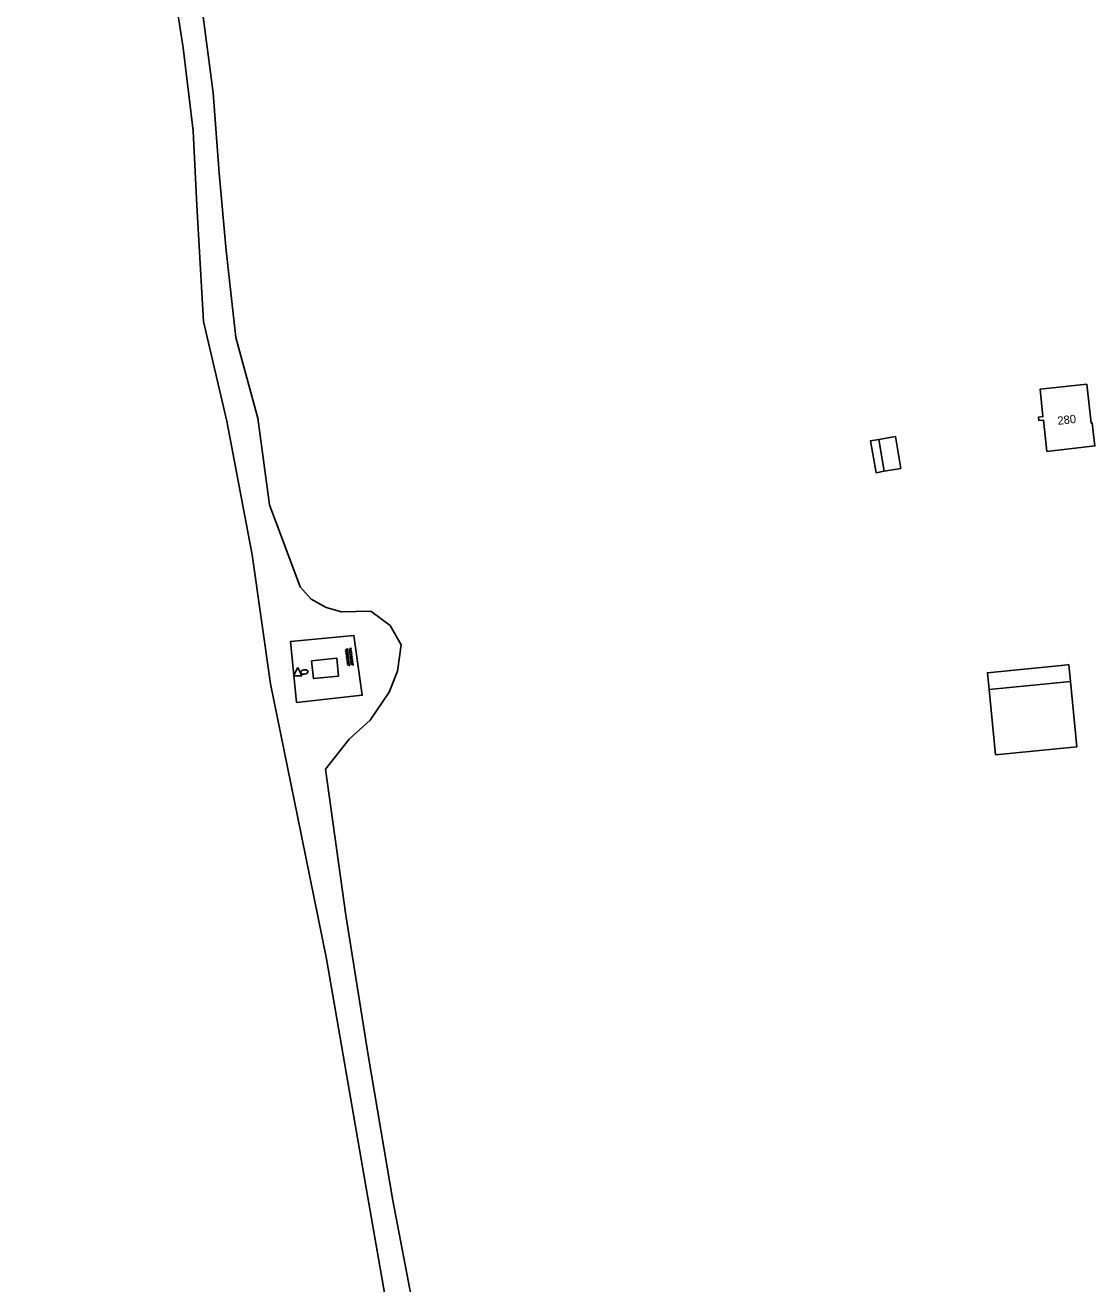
# Model space of a CAD drawing. Extents: x 128999 to 131010, y 395498 to 399007.
# Drawn here: x 129239.4 to 129368.2, y 395802.9 to 395954.5 of the extents above; entities that cross this region are included whole.
import ezdxf

# ---------------------------------------------------------------- set-up
doc = ezdxf.new("R2010")
doc.units = 0
for name, color, linetype in [('gg-anno-huisnummerreeks BGT', 7, 'Continuous'), ('gg-bbg-bijgebouw', 7, 'Continuous'), ('gg-bbg-hoofdgebouw', 7, 'Continuous'), ('gg-bbg-luifel en loopbrug', 7, 'Continuous'), ('gg-knt-onverhard', 7, 'Continuous'), ('gg-kwrk-betonelement', 7, 'Continuous'), ('gt-symb-brandkraan', 7, 'Continuous'), ('gt-symb-overige verharding', 7, 'Continuous'), ('gt-symb-waterafsluiter', 7, 'Continuous')]:
    doc.layers.add(name, color=color, linetype=linetype)

# ---------------------------------------------------------------- blocks, each defined once
blk = doc.blocks.new('gt0-WAFSL')
at = {"layer": 'gt-symb-waterafsluiter'}
for p, q in [((-0.5, -0.33), (0, 0.67)), ((0, 0.67), (0.5, -0.33)), ((0.5, -0.33), (-0.5, -0.33))]:
    blk.add_line(p, q, dxfattribs=at)
blk = doc.blocks.new('gt0-BR')
at = {"layer": 'gt-symb-brandkraan'}
for centre, radius, start, end in [((-0.24, 0), 0.206, 107.5669, 252.4331), ((0.6, -2.66), 3, 106.892, 107.5669), ((0, -0.69), 0.938, 73.108, 106.892), ((-0.6, -2.66), 3, 72.4331, 73.108), ((0.24, 0), 0.206, 287.567, 72.4331), ((0.6, 2.66), 3, 252.4331, 253.108), ((0, 0.69), 0.938, 253.108, 286.8921), ((-0.6, 2.66), 3, 286.8921, 287.567)]:
    blk.add_arc(centre, radius, start, end, dxfattribs=at)
blk = doc.blocks.new('gt0-OVH')
at = {"layer": 'gt-symb-overige verharding'}
for points in [[(-0.97, 0.3), (-0.97, 0.31), (-0.96, 0.32), (-0.97, 0.33), (-0.97, 0.34), (-0.98, 0.35), (-0.99, 0.35), (-1, 0.36), (-1.01, 0.35), (-1.02, 0.35), (-1.03, 0.34), (-1.03, 0.33), (-1.04, 0.32), (-1.03, 0.31), (-1.03, 0.3), (-1.02, 0.29), (-1.01, 0.29), (-1, 0.28), (-0.99, 0.29), (-0.98, 0.29)], [(-0.87, 0.11), (-0.87, 0.12), (-0.86, 0.13), (-0.87, 0.14), (-0.87, 0.15), (-0.88, 0.16), (-0.89, 0.16), (-0.9, 0.16), (-0.91, 0.16), (-0.92, 0.16), (-0.93, 0.15), (-0.93, 0.14), (-0.94, 0.13), (-0.93, 0.12), (-0.93, 0.11), (-0.92, 0.1), (-0.91, 0.09), (-0.9, 0.09), (-0.89, 0.09), (-0.88, 0.1)], [(-0.77, 0.3), (-0.77, 0.31), (-0.76, 0.32), (-0.77, 0.33), (-0.77, 0.34), (-0.78, 0.35), (-0.79, 0.35), (-0.8, 0.36), (-0.81, 0.35), (-0.82, 0.35), (-0.83, 0.34), (-0.83, 0.33), (-0.84, 0.32), (-0.83, 0.31), (-0.83, 0.3), (-0.82, 0.29), (-0.81, 0.29), (-0.8, 0.28), (-0.79, 0.29), (-0.78, 0.29)], [(-0.67, 0.11), (-0.67, 0.12), (-0.66, 0.13), (-0.67, 0.14), (-0.67, 0.15), (-0.68, 0.16), (-0.69, 0.16), (-0.7, 0.16), (-0.71, 0.16), (-0.72, 0.16), (-0.73, 0.15), (-0.73, 0.14), (-0.74, 0.13), (-0.73, 0.12), (-0.73, 0.11), (-0.72, 0.1), (-0.71, 0.09), (-0.7, 0.09), (-0.69, 0.09), (-0.68, 0.1)], [(-0.57, 0.3), (-0.57, 0.31), (-0.56, 0.32), (-0.57, 0.33), (-0.57, 0.34), (-0.58, 0.35), (-0.59, 0.35), (-0.6, 0.36), (-0.61, 0.35), (-0.62, 0.35), (-0.63, 0.34), (-0.63, 0.33), (-0.64, 0.32), (-0.63, 0.31), (-0.63, 0.3), (-0.62, 0.29), (-0.61, 0.29), (-0.6, 0.28), (-0.59, 0.29), (-0.58, 0.29)], [(-0.47, 0.11), (-0.47, 0.12), (-0.46, 0.13), (-0.47, 0.14), (-0.47, 0.15), (-0.48, 0.16), (-0.49, 0.16), (-0.5, 0.16), (-0.51, 0.16), (-0.52, 0.16), (-0.53, 0.15), (-0.53, 0.14), (-0.54, 0.13), (-0.53, 0.12), (-0.53, 0.11), (-0.52, 0.1), (-0.51, 0.09), (-0.5, 0.09), (-0.49, 0.09), (-0.48, 0.1)], [(-0.37, 0.3), (-0.37, 0.31), (-0.36, 0.32), (-0.37, 0.33), (-0.37, 0.34), (-0.38, 0.35), (-0.39, 0.35), (-0.4, 0.36), (-0.41, 0.35), (-0.42, 0.35), (-0.43, 0.34), (-0.43, 0.33), (-0.44, 0.32), (-0.43, 0.31), (-0.43, 0.3), (-0.42, 0.29), (-0.41, 0.29), (-0.4, 0.28), (-0.39, 0.29), (-0.38, 0.29)], [(-0.27, 0.11), (-0.27, 0.12), (-0.26, 0.13), (-0.27, 0.14), (-0.27, 0.15), (-0.28, 0.16), (-0.29, 0.16), (-0.3, 0.16), (-0.31, 0.16), (-0.32, 0.16), (-0.33, 0.15), (-0.33, 0.14), (-0.34, 0.13), (-0.33, 0.12), (-0.33, 0.11), (-0.32, 0.1), (-0.31, 0.09), (-0.3, 0.09), (-0.29, 0.09), (-0.28, 0.1)], [(-0.17, 0.3), (-0.17, 0.31), (-0.16, 0.32), (-0.17, 0.33), (-0.17, 0.34), (-0.18, 0.35), (-0.19, 0.35), (-0.2, 0.36), (-0.21, 0.35), (-0.22, 0.35), (-0.23, 0.34), (-0.23, 0.33), (-0.24, 0.32), (-0.23, 0.31), (-0.23, 0.3), (-0.22, 0.29), (-0.21, 0.29), (-0.2, 0.28), (-0.19, 0.29), (-0.18, 0.29)], [(-0.07, 0.11), (-0.07, 0.12), (-0.06, 0.13), (-0.07, 0.14), (-0.07, 0.15), (-0.08, 0.16), (-0.09, 0.16), (-0.1, 0.16), (-0.11, 0.16), (-0.12, 0.16), (-0.13, 0.15), (-0.13, 0.14), (-0.14, 0.13), (-0.13, 0.12), (-0.13, 0.11), (-0.12, 0.1), (-0.11, 0.09), (-0.1, 0.09), (-0.09, 0.09), (-0.08, 0.1)], [(0.03, 0.3), (0.03, 0.31), (0.04, 0.32), (0.03, 0.33), (0.03, 0.34), (0.02, 0.35), (0.01, 0.35), (0, 0.36), (-0.01, 0.35), (-0.02, 0.35), (-0.03, 0.34), (-0.03, 0.33), (-0.04, 0.32), (-0.03, 0.31), (-0.03, 0.3), (-0.02, 0.29), (-0.01, 0.29), (0, 0.28), (0.01, 0.29), (0.02, 0.29)], [(0.13, 0.11), (0.13, 0.12), (0.14, 0.13), (0.13, 0.14), (0.13, 0.15), (0.12, 0.16), (0.11, 0.16), (0.1, 0.16), (0.09, 0.16), (0.08, 0.16), (0.07, 0.15), (0.07, 0.14), (0.06, 0.13), (0.07, 0.12), (0.07, 0.11), (0.08, 0.1), (0.09, 0.09), (0.1, 0.09), (0.11, 0.09), (0.12, 0.1)], [(0.23, 0.3), (0.23, 0.31), (0.24, 0.32), (0.23, 0.33), (0.23, 0.34), (0.22, 0.35), (0.21, 0.35), (0.2, 0.36), (0.19, 0.35), (0.18, 0.35), (0.17, 0.34), (0.17, 0.33), (0.16, 0.32), (0.17, 0.31), (0.17, 0.3), (0.18, 0.29), (0.19, 0.29), (0.2, 0.28), (0.21, 0.29), (0.22, 0.29)], [(0.33, 0.11), (0.33, 0.12), (0.34, 0.13), (0.33, 0.14), (0.33, 0.15), (0.32, 0.16), (0.31, 0.16), (0.3, 0.16), (0.29, 0.16), (0.28, 0.16), (0.27, 0.15), (0.27, 0.14), (0.26, 0.13), (0.27, 0.12), (0.27, 0.11), (0.28, 0.1), (0.29, 0.09), (0.3, 0.09), (0.31, 0.09), (0.32, 0.1)], [(0.43, 0.3), (0.43, 0.31), (0.44, 0.32), (0.43, 0.33), (0.43, 0.34), (0.42, 0.35), (0.41, 0.35), (0.4, 0.36), (0.39, 0.35), (0.38, 0.35), (0.37, 0.34), (0.37, 0.33), (0.36, 0.32), (0.37, 0.31), (0.37, 0.3), (0.38, 0.29), (0.39, 0.29), (0.4, 0.28), (0.41, 0.29), (0.42, 0.29)], [(0.53, 0.11), (0.53, 0.12), (0.54, 0.13), (0.53, 0.14), (0.53, 0.15), (0.52, 0.16), (0.51, 0.16), (0.5, 0.16), (0.49, 0.16), (0.48, 0.16), (0.47, 0.15), (0.47, 0.14), (0.46, 0.13), (0.47, 0.12), (0.47, 0.11), (0.48, 0.1), (0.49, 0.09), (0.5, 0.09), (0.51, 0.09), (0.52, 0.1)], [(0.63, 0.3), (0.63, 0.31), (0.64, 0.32), (0.63, 0.33), (0.63, 0.34), (0.62, 0.35), (0.61, 0.35), (0.6, 0.36), (0.59, 0.35), (0.58, 0.35), (0.57, 0.34), (0.57, 0.33), (0.56, 0.32), (0.57, 0.31), (0.57, 0.3), (0.58, 0.29), (0.59, 0.29), (0.6, 0.28), (0.61, 0.29), (0.62, 0.29)], [(0.73, 0.11), (0.73, 0.12), (0.74, 0.13), (0.73, 0.14), (0.73, 0.15), (0.72, 0.16), (0.71, 0.16), (0.7, 0.16), (0.69, 0.16), (0.68, 0.16), (0.67, 0.15), (0.67, 0.14), (0.66, 0.13), (0.67, 0.12), (0.67, 0.11), (0.68, 0.1), (0.69, 0.09), (0.7, 0.09), (0.71, 0.09), (0.72, 0.1)], [(0.83, 0.3), (0.83, 0.31), (0.84, 0.32), (0.83, 0.33), (0.83, 0.34), (0.82, 0.35), (0.81, 0.35), (0.8, 0.36), (0.79, 0.35), (0.78, 0.35), (0.77, 0.34), (0.77, 0.33), (0.76, 0.32), (0.77, 0.31), (0.77, 0.3), (0.78, 0.29), (0.79, 0.29), (0.8, 0.28), (0.81, 0.29), (0.82, 0.29)], [(0.93, 0.11), (0.93, 0.12), (0.94, 0.13), (0.93, 0.14), (0.93, 0.15), (0.92, 0.16), (0.91, 0.16), (0.9, 0.16), (0.89, 0.16), (0.88, 0.16), (0.87, 0.15), (0.87, 0.14), (0.86, 0.13), (0.87, 0.12), (0.87, 0.11), (0.88, 0.1), (0.89, 0.09), (0.9, 0.09), (0.91, 0.09), (0.92, 0.1)], [(1.03, 0.3), (1.03, 0.31), (1.04, 0.32), (1.03, 0.33), (1.03, 0.34), (1.02, 0.35), (1.01, 0.35), (1, 0.36), (0.99, 0.35), (0.98, 0.35), (0.97, 0.34), (0.97, 0.33), (0.96, 0.32), (0.97, 0.31), (0.97, 0.3), (0.98, 0.29), (0.99, 0.29), (1, 0.28), (1.01, 0.29), (1.02, 0.29)], [(-0.97, -0.14), (-0.97, -0.13), (-0.96, -0.12), (-0.97, -0.11), (-0.97, -0.1), (-0.98, -0.09), (-0.99, -0.09), (-1, -0.08), (-1.01, -0.09), (-1.02, -0.09), (-1.03, -0.1), (-1.03, -0.11), (-1.04, -0.12), (-1.03, -0.13), (-1.03, -0.14), (-1.02, -0.15), (-1.01, -0.15), (-1, -0.16), (-0.99, -0.15), (-0.98, -0.15)], [(-0.87, -0.33), (-0.87, -0.32), (-0.86, -0.31), (-0.87, -0.3), (-0.87, -0.29), (-0.88, -0.28), (-0.89, -0.28), (-0.9, -0.28), (-0.91, -0.28), (-0.92, -0.28), (-0.93, -0.29), (-0.93, -0.3), (-0.94, -0.31), (-0.93, -0.32), (-0.93, -0.33), (-0.92, -0.34), (-0.91, -0.35), (-0.9, -0.35), (-0.89, -0.35), (-0.88, -0.34)], [(-0.77, -0.14), (-0.77, -0.13), (-0.76, -0.12), (-0.77, -0.11), (-0.77, -0.1), (-0.78, -0.09), (-0.79, -0.09), (-0.8, -0.08), (-0.81, -0.09), (-0.82, -0.09), (-0.83, -0.1), (-0.83, -0.11), (-0.84, -0.12), (-0.83, -0.13), (-0.83, -0.14), (-0.82, -0.15), (-0.81, -0.15), (-0.8, -0.16), (-0.79, -0.15), (-0.78, -0.15)], [(-0.67, -0.33), (-0.67, -0.32), (-0.66, -0.31), (-0.67, -0.3), (-0.67, -0.29), (-0.68, -0.28), (-0.69, -0.28), (-0.7, -0.28), (-0.71, -0.28), (-0.72, -0.28), (-0.73, -0.29), (-0.73, -0.3), (-0.74, -0.31), (-0.73, -0.32), (-0.73, -0.33), (-0.72, -0.34), (-0.71, -0.35), (-0.7, -0.35), (-0.69, -0.35), (-0.68, -0.34)], [(-0.57, -0.14), (-0.57, -0.13), (-0.56, -0.12), (-0.57, -0.11), (-0.57, -0.1), (-0.58, -0.09), (-0.59, -0.09), (-0.6, -0.08), (-0.61, -0.09), (-0.62, -0.09), (-0.63, -0.1), (-0.63, -0.11), (-0.64, -0.12), (-0.63, -0.13), (-0.63, -0.14), (-0.62, -0.15), (-0.61, -0.15), (-0.6, -0.16), (-0.59, -0.15), (-0.58, -0.15)], [(-0.47, -0.33), (-0.47, -0.32), (-0.46, -0.31), (-0.47, -0.3), (-0.47, -0.29), (-0.48, -0.28), (-0.49, -0.28), (-0.5, -0.28), (-0.51, -0.28), (-0.52, -0.28), (-0.53, -0.29), (-0.53, -0.3), (-0.54, -0.31), (-0.53, -0.32), (-0.53, -0.33), (-0.52, -0.34), (-0.51, -0.35), (-0.5, -0.35), (-0.49, -0.35), (-0.48, -0.34)], [(-0.37, -0.14), (-0.37, -0.13), (-0.36, -0.12), (-0.37, -0.11), (-0.37, -0.1), (-0.38, -0.09), (-0.39, -0.09), (-0.4, -0.08), (-0.41, -0.09), (-0.42, -0.09), (-0.43, -0.1), (-0.43, -0.11), (-0.44, -0.12), (-0.43, -0.13), (-0.43, -0.14), (-0.42, -0.15), (-0.41, -0.15), (-0.4, -0.16), (-0.39, -0.15), (-0.38, -0.15)], [(-0.27, -0.33), (-0.27, -0.32), (-0.26, -0.31), (-0.27, -0.3), (-0.27, -0.29), (-0.28, -0.28), (-0.29, -0.28), (-0.3, -0.28), (-0.31, -0.28), (-0.32, -0.28), (-0.33, -0.29), (-0.33, -0.3), (-0.34, -0.31), (-0.33, -0.32), (-0.33, -0.33), (-0.32, -0.34), (-0.31, -0.35), (-0.3, -0.35), (-0.29, -0.35), (-0.28, -0.34)], [(-0.17, -0.14), (-0.17, -0.13), (-0.16, -0.12), (-0.17, -0.11), (-0.17, -0.1), (-0.18, -0.09), (-0.19, -0.09), (-0.2, -0.08), (-0.21, -0.09), (-0.22, -0.09), (-0.23, -0.1), (-0.23, -0.11), (-0.24, -0.12), (-0.23, -0.13), (-0.23, -0.14), (-0.22, -0.15), (-0.21, -0.15), (-0.2, -0.16), (-0.19, -0.15), (-0.18, -0.15)], [(-0.07, -0.33), (-0.07, -0.32), (-0.06, -0.31), (-0.07, -0.3), (-0.07, -0.29), (-0.08, -0.28), (-0.09, -0.28), (-0.1, -0.28), (-0.11, -0.28), (-0.12, -0.28), (-0.13, -0.29), (-0.13, -0.3), (-0.14, -0.31), (-0.13, -0.32), (-0.13, -0.33), (-0.12, -0.34), (-0.11, -0.35), (-0.1, -0.35), (-0.09, -0.35), (-0.08, -0.34)], [(0.03, -0.14), (0.03, -0.13), (0.04, -0.12), (0.03, -0.11), (0.03, -0.1), (0.02, -0.09), (0.01, -0.09), (0, -0.08), (-0.01, -0.09), (-0.02, -0.09), (-0.03, -0.1), (-0.03, -0.11), (-0.04, -0.12), (-0.03, -0.13), (-0.03, -0.14), (-0.02, -0.15), (-0.01, -0.15), (0, -0.16), (0.01, -0.15), (0.02, -0.15)], [(0.13, -0.33), (0.13, -0.32), (0.14, -0.31), (0.13, -0.3), (0.13, -0.29), (0.12, -0.28), (0.11, -0.28), (0.1, -0.28), (0.09, -0.28), (0.08, -0.28), (0.07, -0.29), (0.07, -0.3), (0.06, -0.31), (0.07, -0.32), (0.07, -0.33), (0.08, -0.34), (0.09, -0.35), (0.1, -0.35), (0.11, -0.35), (0.12, -0.34)], [(0.23, -0.14), (0.23, -0.13), (0.24, -0.12), (0.23, -0.11), (0.23, -0.1), (0.22, -0.09), (0.21, -0.09), (0.2, -0.08), (0.19, -0.09), (0.18, -0.09), (0.17, -0.1), (0.17, -0.11), (0.16, -0.12), (0.17, -0.13), (0.17, -0.14), (0.18, -0.15), (0.19, -0.15), (0.2, -0.16), (0.21, -0.15), (0.22, -0.15)], [(0.33, -0.33), (0.33, -0.32), (0.34, -0.31), (0.33, -0.3), (0.33, -0.29), (0.32, -0.28), (0.31, -0.28), (0.3, -0.28), (0.29, -0.28), (0.28, -0.28), (0.27, -0.29), (0.27, -0.3), (0.26, -0.31), (0.27, -0.32), (0.27, -0.33), (0.28, -0.34), (0.29, -0.35), (0.3, -0.35), (0.31, -0.35), (0.32, -0.34)], [(0.43, -0.14), (0.43, -0.13), (0.44, -0.12), (0.43, -0.11), (0.43, -0.1), (0.42, -0.09), (0.41, -0.09), (0.4, -0.08), (0.39, -0.09), (0.38, -0.09), (0.37, -0.1), (0.37, -0.11), (0.36, -0.12), (0.37, -0.13), (0.37, -0.14), (0.38, -0.15), (0.39, -0.15), (0.4, -0.16), (0.41, -0.15), (0.42, -0.15)], [(0.53, -0.33), (0.53, -0.32), (0.54, -0.31), (0.53, -0.3), (0.53, -0.29), (0.52, -0.28), (0.51, -0.28), (0.5, -0.28), (0.49, -0.28), (0.48, -0.28), (0.47, -0.29), (0.47, -0.3), (0.46, -0.31), (0.47, -0.32), (0.47, -0.33), (0.48, -0.34), (0.49, -0.35), (0.5, -0.35), (0.51, -0.35), (0.52, -0.34)], [(0.63, -0.14), (0.63, -0.13), (0.64, -0.12), (0.63, -0.11), (0.63, -0.1), (0.62, -0.09), (0.61, -0.09), (0.6, -0.08), (0.59, -0.09), (0.58, -0.09), (0.57, -0.1), (0.57, -0.11), (0.56, -0.12), (0.57, -0.13), (0.57, -0.14), (0.58, -0.15), (0.59, -0.15), (0.6, -0.16), (0.61, -0.15), (0.62, -0.15)], [(0.73, -0.33), (0.73, -0.32), (0.74, -0.31), (0.73, -0.3), (0.73, -0.29), (0.72, -0.28), (0.71, -0.28), (0.7, -0.28), (0.69, -0.28), (0.68, -0.28), (0.67, -0.29), (0.67, -0.3), (0.66, -0.31), (0.67, -0.32), (0.67, -0.33), (0.68, -0.34), (0.69, -0.35), (0.7, -0.35), (0.71, -0.35), (0.72, -0.34)], [(0.83, -0.14), (0.83, -0.13), (0.84, -0.12), (0.83, -0.11), (0.83, -0.1), (0.82, -0.09), (0.81, -0.09), (0.8, -0.08), (0.79, -0.09), (0.78, -0.09), (0.77, -0.1), (0.77, -0.11), (0.76, -0.12), (0.77, -0.13), (0.77, -0.14), (0.78, -0.15), (0.79, -0.15), (0.8, -0.16), (0.81, -0.15), (0.82, -0.15)], [(0.93, -0.33), (0.93, -0.32), (0.94, -0.31), (0.93, -0.3), (0.93, -0.29), (0.92, -0.28), (0.91, -0.28), (0.9, -0.28), (0.89, -0.28), (0.88, -0.28), (0.87, -0.29), (0.87, -0.3), (0.86, -0.31), (0.87, -0.32), (0.87, -0.33), (0.88, -0.34), (0.89, -0.35), (0.9, -0.35), (0.91, -0.35), (0.92, -0.34)], [(1.03, -0.14), (1.03, -0.13), (1.04, -0.12), (1.03, -0.11), (1.03, -0.1), (1.02, -0.09), (1.01, -0.09), (1, -0.08), (0.99, -0.09), (0.98, -0.09), (0.97, -0.1), (0.97, -0.11), (0.96, -0.12), (0.97, -0.13), (0.97, -0.14), (0.98, -0.15), (0.99, -0.15), (1, -0.16), (1.01, -0.15), (1.02, -0.15)]]:
    blk.add_lwpolyline(points, close=True, dxfattribs=at)

msp = doc.modelspace()

# ---------------------------------------------------------------- linework, layer by layer
at = {"layer": 'gg-bbg-bijgebouw'}
for p, q in [((129342.87, 395900.79), (129342.21, 395904.64)), ((129355.51, 395874.51), (129365.31, 395875.49))]:
    msp.add_line(p, q, dxfattribs=at)
for points in [[(129342.21, 395904.64), (129344.22, 395904.98), (129344.87, 395901.13), (129342.87, 395900.79)], [(129355.51, 395874.51), (129356.29, 395866.65), (129366.09, 395867.63), (129365.31, 395875.49)]]:
    msp.add_lwpolyline(points, dxfattribs=at)
at = {"layer": 'gg-bbg-hoofdgebouw'}
msp.add_lwpolyline([(129367.29, 395911.3), (129367.81, 395906.58), (129367.94, 395906.59), (129368.25, 395903.84), (129362.48, 395903.19), (129362.06, 395906.95), (129361.51, 395906.89), (129361.47, 395907.32), (129362, 395907.38), (129361.65, 395910.67), (129367.29, 395911.3)], dxfattribs=at)
at = {"layer": 'gg-bbg-luifel en loopbrug'}
for points in [[(129342.87, 395900.79), (129341.89, 395900.62), (129341.23, 395904.47), (129342.21, 395904.64)], [(129365.31, 395875.49), (129365.11, 395877.51), (129364.61, 395877.46), (129355.31, 395876.53), (129355.51, 395874.51)]]:
    msp.add_lwpolyline(points, dxfattribs=at)
at = {"layer": 'gg-knt-onverhard'}
for points in [[(129239.4, 396088.51), (129241.22, 396064.78), (129242.57, 396053.41), (129244.01, 396042.94), (129246.02, 396033.39), (129247.63, 396024.26), (129249.37, 396013.85), (129250.46, 396003.98), (129250.95, 395995.65), (129251.63, 395985.72), (129254.05, 395976.91), (129255.92, 395968.12), (129258.44, 395951.79), (129259.65, 395941.8), (129260.06, 395932.78), (129260.87, 395918.85), (129263.68, 395906.84), (129266.73, 395890.74), (129268.94, 395875.21), (129272.22, 395859.26), (129275.7, 395842.08), (129280.23, 395815.86), (129283.3, 395798.42)], [(129287.01, 395795.59), (129283.68, 395813), (129280.76, 395830.25), (129278.02, 395847.36), (129275.58, 395864.94), (129278.41, 395868.55), (129280.95, 395870.84), (129283.23, 395874.2), (129284.25, 395876.72), (129284.71, 395879.88), (129283.36, 395882.22), (129281.03, 395883.96), (129277.49, 395883.87), (129275.65, 395884.39), (129273.85, 395885.4), (129272.51, 395886.86), (129268.82, 395896.77), (129267.43, 395907.19), (129264.79, 395916.89), (129263.6, 395927.4), (129262.75, 395936.71), (129262.03, 395946.35), (129260.84, 395955.52)], [(129272.07, 395872.95), (129280, 395873.82), (129278.99, 395881.02), (129271.36, 395880.3), (129272.07, 395872.95)]]:
    msp.add_lwpolyline(points, dxfattribs=at)
at = {"layer": 'gg-kwrk-betonelement'}
msp.add_lwpolyline([(129277.16, 395876.12), (129276.94, 395878.3), (129273.89, 395877.96), (129274.12, 395875.83), (129277.16, 395876.12)], dxfattribs=at)

# ---------------------------------------------------------------- block references
at = {"layer": 'gt-symb-brandkraan', "rotation": 8.15406927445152}
msp.add_blockref('gt0-BR', (129273.02, 395876.62), dxfattribs=at)
at = {"layer": 'gt-symb-overige verharding', "rotation": -82.41293092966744}
msp.add_blockref('gt0-OVH', (129278.44, 395878.43), dxfattribs=at)
at = {"layer": 'gt-symb-waterafsluiter'}
msp.add_blockref('gt0-WAFSL', (129272.23, 395876.5), dxfattribs=at)

# ---------------------------------------------------------------- texts
at = {"layer": 'gg-anno-huisnummerreeks BGT'}
msp.add_text('280', height=1, rotation=6.4, dxfattribs=at).set_placement((129363.81, 395906.38))

doc.saveas('drawing.dxf')
